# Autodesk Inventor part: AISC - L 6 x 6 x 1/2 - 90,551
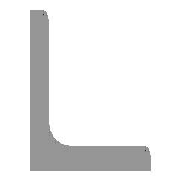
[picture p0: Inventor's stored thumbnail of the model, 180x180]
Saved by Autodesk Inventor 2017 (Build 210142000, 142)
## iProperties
_CCFamilyMember: 47
_CCFamilyDisplayName: ANSI L (Kątownik równoramienny) - Kątownik — Rozmiary w nawiasach zostały wycofane
_FrameMemberDoc: Frame Member File
_Version: 15.0.0
_GetPNFromCC: 1
Created: 2016-02
Part Number: AISC - L 6 x 6 x 1/2 - 90,551
Material: Stal, miękka
Description: Kątownik
Document SubType Name: Modeling
Standard: ANSI
Designer: X
Standards Organization: ANSI
Language: pl-PL
Size Designation: L 6 x 6 x 1/2
Categories: <MemberInstance><Categories><Category DisplayName="Kształtowniki konstrukcyjne" InternalName="089c4875-fa83-4c05-b084-43b9cc11f5ed" Mnemonic="GRDR"><CategoryPar
Stock Number: L 6 x 6 x 1/2
Density: 7.85 g/cm^3
Appearance: Częściowo polerowana
IsCustomPart: 1
G_L: 2300,000 mm
G_W: 152,400 mm
G_H: 152,400 mm
Author: X
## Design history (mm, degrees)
node "Płaszczyzna początkowa"
node "Płaszczyzna końcowa"
sketch "Szkic"
  geometry: L1 (152.4, 0)-(0, 0); L2 (0, 0)-(0, 152.4); L3 (0, 152.4)-(6.35, 152.4); L4 (12.7, 146.05)-(12.7, 25.4); L5 (25.4, 12.7)-(146.05, 12.7); L6 (152.4, 6.35)-(152.4, 0); L7 (0, -11.041)-(0, 31.538); L8 (-11.041, 0)-(31.538, 0); L9 (0, 186.666)-(0, -43.993) reference; L10 (-43.993, 0)-(186.666, 0) reference; A1 r 12.7 centre (25.4, 25.4) between (12.7, 25.4) and (25.4, 12.7); A2 r 6.35 centre (6.35, 146.05) between (12.7, 146.05) and (6.35, 152.4); A3 r 6.35 centre (146.05, 6.35) between (152.4, 6.35) and (146.05, 12.7); 3 further points
  constraints: 16 end point, 6 point on circle, 6 point on line, 6 tangent, 4 parallel, 3 centre point, 2 collinear, 1 equal radius, 1 horizontal, 1 perpendicular
  dimensions: "d0" = 152.4 distance between parallel lines of L6 L2 (= G_H); "d1" = 152.4 distance between parallel lines of L3 L1 (= G_H); "d2" = 12.7 distance between parallel lines of L2 L4 (= G_T); "d3" = 12.7 distance between parallel lines of L1 L5 (= G_T); "d10" = 0 distance between parallel lines of L7 L2 (computed from ex); "d11" = 0 distance between parallel lines of L8 L1 (computed from d10); "d14" = 12.7 radius of A1 (= G_IR); "d15" = 6.35 radius of A2 (= G_ER)
extrude "Bryła" new body sketch "Szkic" stored distance "d4" = 2300 (= G_L); taper "d5" = 0 deg
node "Driven Length"
  sketch "Sketch3"
    geometry: L1 (0, 0)-(10, 0) reference
    constraints: 2 end point, 1 horizontal
  workplane "Work Plane3"
  sketch "Sketch4"
    geometry: L1 (-2, 0)-(12, 0) reference; L2 (-2, 2300)-(12, 2300) reference
    dimensions: "d17" = 2300 distance between parallel lines of L1 L2 (derived)
body "Solid1"
other parameters: "G_H" = 152.4 [user parameter; used in 2 equation terms], "G_T" = 12.7 [user parameter; used in 2 equation terms], "G_ER" = 6.35 [user parameter; used in 1 equation term], "G_IR" = 12.7 [user parameter; used in 1 equation term], "G_L" = 2300 (= d17) [user parameter; used in 1 equation term], "ex" = 0 [user parameter; used in 1 equation term], "G_OFFSET_START" = 0 [user parameter; used in 1 equation term], "G_OFFSET_END" = 0 [user parameter; used in 1 equation term], "d12" = 0 (computed from G_OFFSET_START), "d16" = 90 deg, "MAS" = 2.9168 [user parameter]
